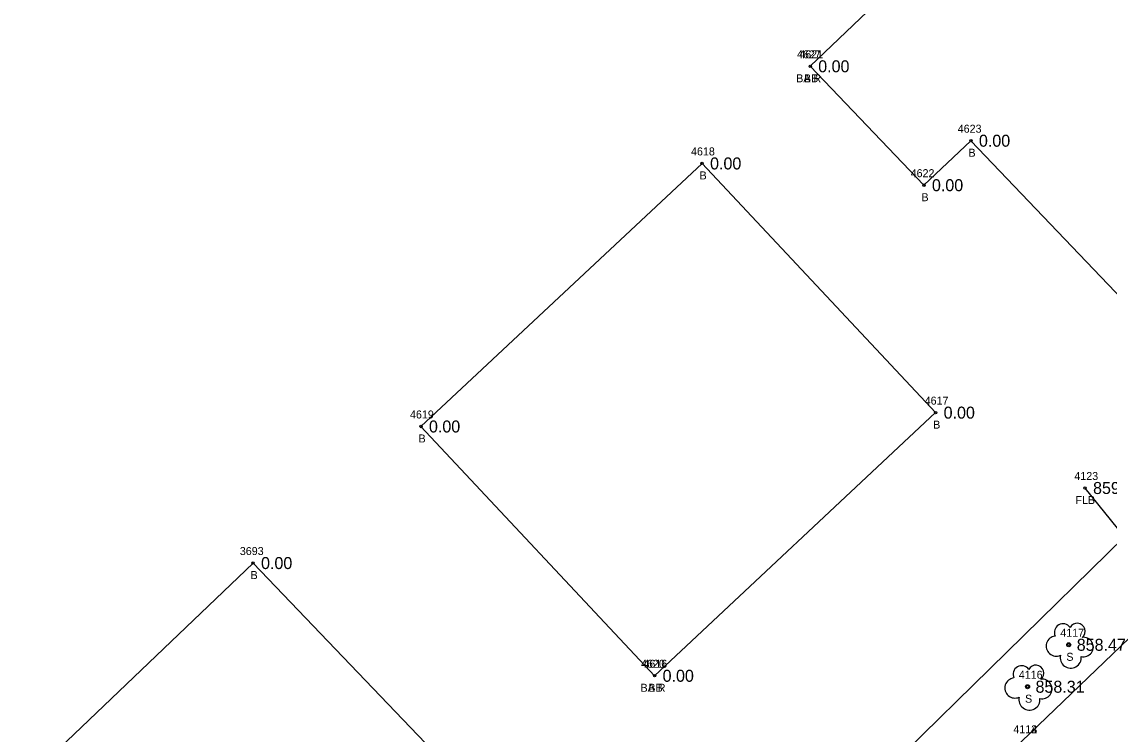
# Model space of a CAD drawing. Extents: x 1622501 to 1626664, y 1117816 to 1121579.
# Drawn here: x 1624827.6 to 1624963.5, y 1120217.8 to 1120306.8 of the extents above; entities that cross this region are included whole.
import ezdxf

# ---------------------------------------------------------------- set-up
doc = ezdxf.new("R2010")
doc.units = 0
for name, color, linetype in [('RD_EX_Bldg', 7, 'Continuous'), ('RD_EX_Bldg_txCode', 7, 'Continuous'), ('RD_EX_Fence_Other', 7, 'Continuous'), ('RD_EX_Fence_Other_txCode', 7, 'Continuous'), ('RD_EX_TX_Bldg_ELEV', 7, 'Continuous'), ('RD_EX_TX_Fence_Other_ELEV', 7, 'Continuous'), ('RD_EX_TX_VEG_ELEV', 7, 'Continuous'), ('RD_EX_VEG', 7, 'Continuous'), ('RD_EX_VEG_txCode', 7, 'Continuous'), ('RD_SMD_Locator', 7, 'Continuous')]:
    doc.layers.add(name, color=color, linetype=linetype)

msp = doc.modelspace()

# ---------------------------------------------------------------- linework, layer by layer
at = {"layer": 'RD_EX_Bldg'}
for points in [[(1624926.13, 1120301.27), (1624940.34, 1120286.41), (1624946.21, 1120291.97), (1624971.49, 1120265.51), (1624999.84, 1120292.31), (1624960.18, 1120333.81), (1624926.13, 1120301.27)], [(1624906.69, 1120225.09), (1624941.8, 1120257.98), (1624912.62, 1120289.13), (1624877.5, 1120256.25), (1624906.69, 1120225.09)], [(1624827.62, 1120211.53), (1624857.59, 1120180.22), (1624886.49, 1120207.88), (1624856.52, 1120239.18), (1624827.62, 1120211.53)]]:
    msp.add_lwpolyline(points, dxfattribs=at)
at = {"layer": 'RD_EX_Fence_Other'}
for points in [[(1624882.11, 1120146.41), (1624922.83, 1120188.17), (1624952.58, 1120216.9), (1624993.86, 1120256.56), (1625030.93, 1120289.64), (1625069.58, 1120326), (1625106.79, 1120358.46), (1625145.39, 1120394.48), (1625163.87, 1120411), (1625180.05, 1120426.7), (1625211.37, 1120456.62), (1625250.44, 1120494.55), (1625284.57, 1120527.63), (1625318.69, 1120557.98), (1625317.76, 1120559.82), (1625354.44, 1120595.49), (1625389.43, 1120629.69)], [(1624858.61, 1120181.16), (1624885.84, 1120153), (1624885.79, 1120151.16), (1624925.79, 1120193.73), (1624921.29, 1120199.2), (1624921.29, 1120199.2), (1624965.41, 1120242.44), (1624960.47, 1120248.56)]]:
    msp.add_lwpolyline(points, dxfattribs=at)
at = {"layer": 'RD_EX_VEG'}
for centre in [(1624958.43, 1120228.96), (1624953.28, 1120223.72)]:
    msp.add_circle(centre, 0.25, dxfattribs=at)
for centre, radius, start, end in [((1624957.71, 1120230.51), 1.08, 34.9763, 204.756), ((1624959.48, 1120230.66), 0.995, 308.7626, 152.0467), ((1624956.87, 1120228.8), 1.26, 96.4518, 294.734), ((1624960.27, 1120228.68), 1.22, 256.5667, 98.1046), ((1624958.68, 1120227.36), 1.32, 166.8827, 5.7589), ((1624952.56, 1120225.27), 1.08, 34.9763, 204.756), ((1624954.32, 1120225.42), 0.995, 308.7626, 152.0467), ((1624951.71, 1120223.56), 1.26, 96.4518, 294.734), ((1624955.12, 1120223.44), 1.22, 256.5667, 98.1046), ((1624953.52, 1120222.12), 1.32, 166.8827, 5.7589)]:
    msp.add_arc(centre, radius, start, end, dxfattribs=at)
at = {"layer": 'RD_SMD_Locator'}
for centre in [(1624926.13, 1120301.27), (1624926.13, 1120301.27), (1624946.21, 1120291.97), (1624912.62, 1120289.13), (1624940.34, 1120286.41), (1624941.8, 1120257.98), (1624877.5, 1120256.25), (1624960.47, 1120248.56), (1624856.52, 1120239.18), (1624958.43, 1120228.96), (1624906.69, 1120225.09), (1624906.69, 1120225.09), (1624953.28, 1120223.72)]:
    msp.add_circle(centre, 0.15, dxfattribs=at)

# ---------------------------------------------------------------- texts
at = {"layer": 'RD_EX_Bldg_txCode'}
for s, p in [('4627', (1624924.48, 1120302.27)), ('4621', (1624924.76, 1120302.27)), ('BA R', (1624924.38, 1120299.27)), ('BB', (1624925.35, 1120299.27)), ('4623', (1624944.56, 1120292.97)), ('4618', (1624911.24, 1120290.13)), ('B', (1624945.9, 1120289.97)), ('B', (1624912.31, 1120287.13)), ('4622', (1624938.68, 1120287.41)), ('B', (1624940.03, 1120284.41)), ('4617', (1624940.43, 1120258.98)), ('4619', (1624876.13, 1120257.25)), ('B', (1624941.49, 1120255.98)), ('B', (1624877.2, 1120254.25)), ('3693', (1624854.87, 1120240.18)), ('B', (1624856.21, 1120237.18)), ('4620', (1624904.99, 1120226.09)), ('4616', (1624905.29, 1120226.09)), ('BA R', (1624904.93, 1120223.09)), ('BB', (1624905.91, 1120223.09))]:
    msp.add_text(s, height=1, dxfattribs=at).set_placement(p)
at = {"layer": 'RD_EX_Fence_Other_txCode'}
for s, p in [('4123', (1624959.13, 1120249.56)), ('FLB', (1624959.27, 1120246.56)), ('4112', (1624951.51, 1120217.9))]:
    msp.add_text(s, height=1, dxfattribs=at).set_placement(p)
at = {"layer": 'RD_EX_TX_Bldg_ELEV'}
for p in [(1624927.13, 1120300.52), (1624927.13, 1120300.52), (1624947.21, 1120291.22), (1624913.62, 1120288.38), (1624941.34, 1120285.66), (1624942.8, 1120257.23), (1624878.5, 1120255.5), (1624857.52, 1120238.43), (1624907.69, 1120224.34), (1624907.69, 1120224.34)]:
    msp.add_text('0.00', height=1.5, dxfattribs=at).set_placement(p)
at = {"layer": 'RD_EX_TX_Fence_Other_ELEV'}
msp.add_text('859.85', height=1.5, dxfattribs=at).set_placement((1624961.47, 1120247.81))
at = {"layer": 'RD_EX_TX_VEG_ELEV'}
for s, p in [('858.47', (1624959.43, 1120228.21)), ('858.31', (1624954.28, 1120222.97))]:
    msp.add_text(s, height=1.5, dxfattribs=at).set_placement(p)
at = {"layer": 'RD_EX_VEG_txCode'}
for s, p in [('4117', (1624957.37, 1120229.96)), ('S', (1624958.13, 1120226.96)), ('4116', (1624952.19, 1120224.72)), ('S', (1624952.97, 1120221.72)), ('4113', (1624951.51, 1120217.9)), ('4114', (1624951.51, 1120217.9))]:
    msp.add_text(s, height=1, dxfattribs=at).set_placement(p)

doc.saveas('drawing.dxf')
